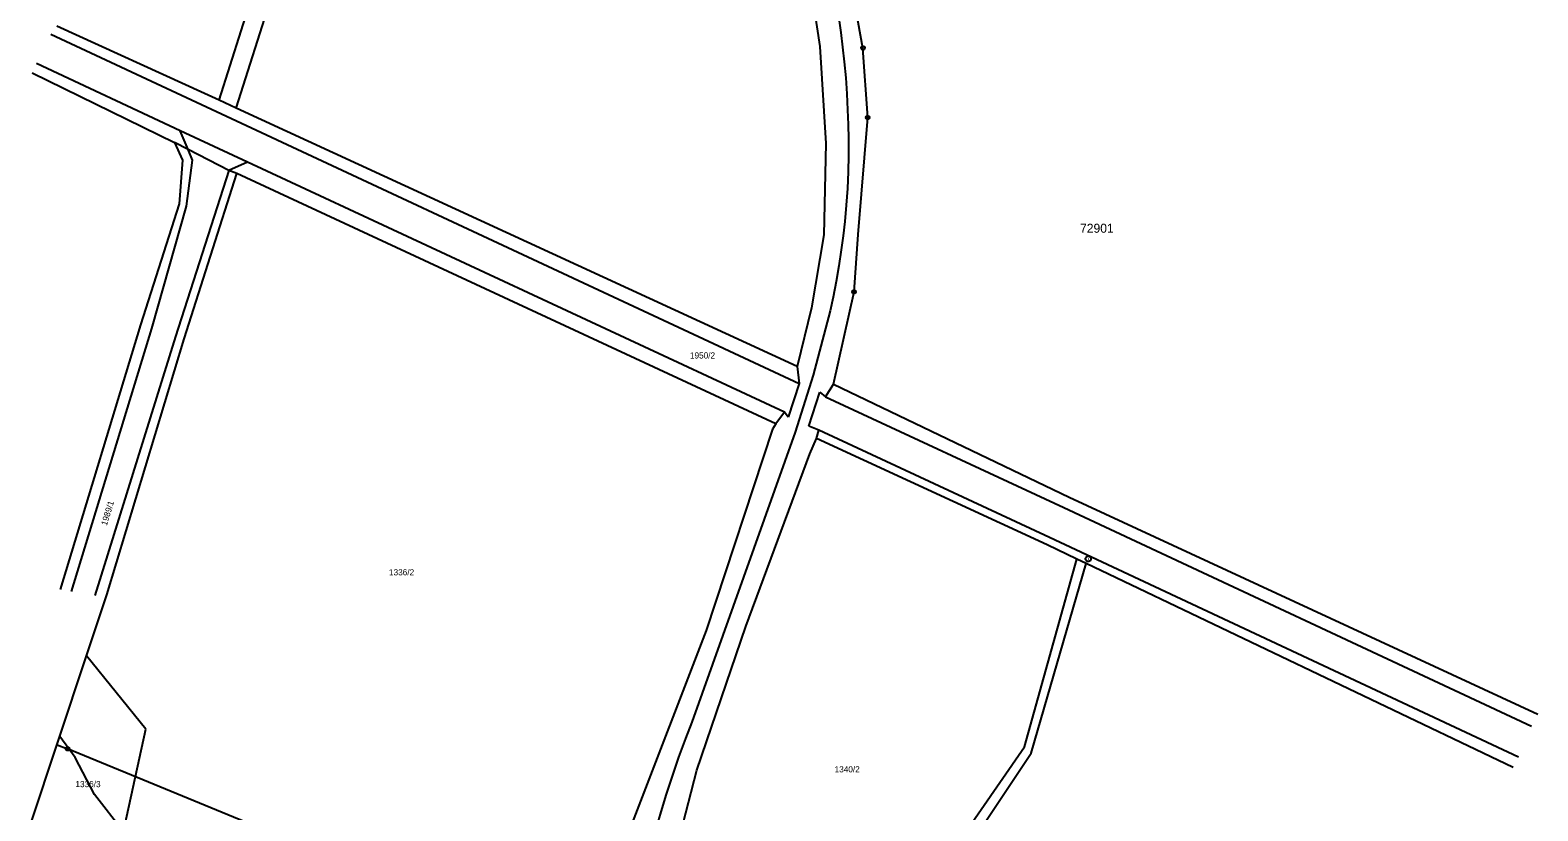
# Model space of a CAD drawing. Extents: x -789470 to -786707, y -1118640 to -1114455.
# Drawn here: x -787470.1 to -787053.8, y -1117519.8 to -1117304.2 of the extents above; entities that cross this region are included whole.
import ezdxf

# ---------------------------------------------------------------- set-up
doc = ezdxf.new("R2010")
doc.units = 0
for name, color, linetype in [('1', 7, 'Continuous'), ('11', 7, 'Continuous'), ('2', 7, 'Continuous'), ('4', 7, 'Continuous'), ('6', 7, 'Continuous'), ('8', 7, 'Continuous')]:
    doc.layers.add(name, color=color, linetype=linetype)

msp = doc.modelspace()

# ---------------------------------------------------------------- linework, layer by layer
at = {"layer": '1'}
for p, q in [((-787417.96, -1117323.48), (-787360.49, -1117143.13)), ((-787413.22, -1117325.67), (-787356.33, -1117146.67)), ((-787255.71, -1117285.12), (-787252.03, -1117308.63)), ((-787240.18, -1117309.09), (-787244.19, -1117287.3)), ((-787422.02, -1117321.61), (-787462.74, -1117303.06)), ((-787252.03, -1117308.63), (-787250.41, -1117335.48)), ((-787238.86, -1117328.3), (-787240.18, -1117309.09)), ((-787469.59, -1117315.99), (-787430.26, -1117335.21)), ((-787417.96, -1117323.48), (-787422.02, -1117321.61)), ((-787413.22, -1117325.67), (-787417.96, -1117323.48)), ((-787258.37, -1117397.06), (-787413.22, -1117325.67)), ((-787241.48, -1117360.62), (-787238.86, -1117328.3)), ((-787430.26, -1117335.21), (-787428.05, -1117340.05)), ((-787426.53, -1117337.12), (-787430.26, -1117335.21)), ((-787250.41, -1117335.48), (-787250.96, -1117360.68)), ((-787415.24, -1117342.91), (-787426.53, -1117337.12)), ((-787428.05, -1117340.05), (-787429.03, -1117352.09)), ((-787427.63, -1117389.42), (-787413.04, -1117343.78)), ((-787413.04, -1117343.78), (-787415.24, -1117342.91)), ((-787264.26, -1117412.91), (-787413.04, -1117343.78)), ((-787429.03, -1117352.09), (-787439.69, -1117385.56)), ((-787250.96, -1117360.68), (-787254.36, -1117380.85)), ((-787242.61, -1117376.43), (-787241.48, -1117360.62)), ((-787248.32, -1117401.92), (-787242.61, -1117376.43)), ((-787254.36, -1117380.85), (-787258.37, -1117397.06)), ((-787439.69, -1117385.56), (-787461.86, -1117458.64)), ((-787448.94, -1117460.1), (-787427.63, -1117389.42)), ((-787258.37, -1117397.06), (-787257.76, -1117401.7)), ((-787257.76, -1117401.7), (-787260.78, -1117411.06)), ((-787250.51, -1117405.41), (-787248.32, -1117401.92)), ((-787248.32, -1117401.92), (-787183.24, -1117433.1)), ((-787255.1, -1117413.5), (-787252.11, -1117404.13)), ((-787252.11, -1117404.13), (-787250.51, -1117405.41)), ((-787261.83, -1117409.67), (-787264.26, -1117412.91)), ((-787260.78, -1117411.06), (-787261.83, -1117409.67)), ((-787265.1, -1117414.39), (-787283.43, -1117469.91)), ((-787264.26, -1117412.91), (-787265.1, -1117414.39)), ((-787252.33, -1117414.61), (-787255.1, -1117413.5)), ((-787252.97, -1117416.89), (-787252.33, -1117414.61)), ((-787254.84, -1117421.14), (-787252.97, -1117416.89)), ((-787189.33, -1117446.27), (-787252.97, -1117416.89)), ((-787272.47, -1117468.81), (-787254.84, -1117421.14)), ((-787183.24, -1117433.1), (-787053.8, -1117493.01)), ((-787181.08, -1117450.22), (-787189.33, -1117446.27)), ((-787195.54, -1117502.09), (-787181.08, -1117450.22)), ((-787193.72, -1117503.85), (-787178.49, -1117451.46)), ((-787178.49, -1117451.46), (-787181.08, -1117450.22)), ((-787060.65, -1117507.79), (-787178.49, -1117451.46)), ((-787454.54, -1117476.95), (-787448.94, -1117460.1)), ((-787286.03, -1117508.52), (-787272.47, -1117468.81)), ((-787283.43, -1117469.91), (-787303.89, -1117523.03)), ((-787470.14, -1117523.83), (-787454.54, -1117476.95)), ((-787438.18, -1117497.19), (-787454.54, -1117476.95)), ((-787448.02, -1117542.27), (-787438.18, -1117497.19)), ((-787270.37, -1117609.83), (-787195.54, -1117502.09)), ((-787265.2, -1117611.01), (-787193.72, -1117503.85)), ((-787297.19, -1117551.99), (-787286.03, -1117508.52))]:
    msp.add_line(p, q, dxfattribs=at)
at = {"layer": '11'}
msp.add_lwpolyline([(-787444.38, -1117525.57), (-787452.36, -1117515.25), (-787457.68, -1117504.99), (-787461.95, -1117499.22), (-787461.95, -1117499.22)], dxfattribs=at)
at = {"layer": '4'}
for p, q in [((-787464.41, -1117305.26), (-787257.76, -1117401.7)), ((-787428.71, -1117331.97), (-787468.36, -1117313.39)), ((-787410.13, -1117340.66), (-787428.71, -1117331.97)), ((-787426.53, -1117337.12), (-787428.71, -1117331.97)), ((-787425.29, -1117340.05), (-787426.53, -1117337.12)), ((-787415.24, -1117342.91), (-787429.99, -1117388.74)), ((-787426.99, -1117352.77), (-787425.29, -1117340.05)), ((-787410.13, -1117340.66), (-787415.24, -1117342.91)), ((-787261.83, -1117409.67), (-787410.13, -1117340.66)), ((-787436.56, -1117386.51), (-787426.99, -1117352.77)), ((-787458.74, -1117459.2), (-787436.56, -1117386.51)), ((-787429.99, -1117388.74), (-787452.26, -1117460.27)), ((-787250.51, -1117405.41), (-787184.71, -1117435.94)), ((-787188.65, -1117444.27), (-787252.33, -1117414.61)), ((-787184.71, -1117435.94), (-787055.59, -1117496.38)), ((-787059.18, -1117504.94), (-787188.65, -1117444.27))]:
    msp.add_line(p, q, dxfattribs=at)
at = {"layer": '6'}
for p, q in [((-787249.2, -1117381.68), (-787253.88, -1117399.41)), ((-787253.88, -1117399.41), (-787258.93, -1117415.14)), ((-787258.93, -1117415.14), (-787287.42, -1117495.28)), ((-787462.71, -1117501.49), (-787459.81, -1117502.65)), ((-787397.87, -1117528.11), (-787459.81, -1117502.65))]:
    msp.add_line(p, q, dxfattribs=at)
for points in [[(-787251.57, -1117278.23), (-787250.57, -1117282.2), (-787249.53, -1117286.69), (-787248.58, -1117291.2), (-787247.73, -1117295.73), (-787246.96, -1117300.28), (-787246.29, -1117304.84), (-787245.78, -1117308.9), (-787245.34, -1117312.88), (-787244.93, -1117317.31), (-787244.62, -1117321.74), (-787244.39, -1117326.17), (-787244.26, -1117330.18)], [(-787244.26, -1117330.18), (-787244.17, -1117334.17), (-787244.17, -1117338.75), (-787244.28, -1117343.32), (-787244.48, -1117347.9), (-787244.79, -1117352.47), (-787245.2, -1117357.03), (-787245.64, -1117360.99), (-787246.14, -1117364.86), (-787246.79, -1117369.21), (-787247.54, -1117373.55), (-787248.37, -1117377.87), (-787249.2, -1117381.68)], [(-787287.42, -1117495.28), (-787289.16, -1117499.78), (-787291.06, -1117504.95), (-787292.86, -1117510.16), (-787294.57, -1117515.39), (-787296.19, -1117520.66), (-787297.52, -1117525.3), (-787298.79, -1117529.97), (-787300.15, -1117535.33), (-787301.41, -1117540.72), (-787302.58, -1117546.13), (-787303.51, -1117550.88)], [(-787459.96, -1117502.17), (-787459.65, -1117502.17), (-787459.4, -1117502.35), (-787459.3, -1117502.64), (-787459.4, -1117502.93), (-787459.65, -1117503.11), (-787459.96, -1117503.11), (-787460.21, -1117502.93), (-787460.31, -1117502.64), (-787460.21, -1117502.35), (-787459.96, -1117502.17), (-787459.93, -1117502.21), (-787459.69, -1117502.21), (-787459.53, -1117502.29), (-787460.09, -1117502.29), (-787460.17, -1117502.37), (-787459.45, -1117502.37), (-787459.45, -1117502.45), (-787460.17, -1117502.45), (-787460.21, -1117502.53), (-787459.41, -1117502.53), (-787459.37, -1117502.61), (-787460.25, -1117502.61), (-787460.25, -1117502.69), (-787459.37, -1117502.69), (-787459.4, -1117502.77), (-787460.21, -1117502.77), (-787460.2, -1117502.85), (-787459.39, -1117502.85), (-787459.44, -1117502.93), (-787460.16, -1117502.93), (-787460.08, -1117503.01), (-787459.52, -1117503.01), (-787459.63, -1117503.09), (-787459.97, -1117503.09)]]:
    msp.add_lwpolyline(points, dxfattribs=at)
at = {"layer": '8'}
for p, q in [((-787240.3, -1117309.09), (-787240.06, -1117309.09)), ((-787238.98, -1117328.3), (-787238.74, -1117328.3)), ((-787242.73, -1117376.43), (-787242.49, -1117376.43)), ((-787177.99, -1117450.16), (-787177.89, -1117450.16))]:
    msp.add_line(p, q, dxfattribs=at)
for points in [[(-787240.03, -1117308.61), (-787239.78, -1117308.79), (-787239.68, -1117309.08), (-787239.78, -1117309.37), (-787240.03, -1117309.55), (-787240.34, -1117309.55), (-787240.59, -1117309.37), (-787240.69, -1117309.08), (-787240.59, -1117308.79), (-787240.34, -1117308.61)], [(-787238.71, -1117327.82), (-787238.46, -1117328), (-787238.36, -1117328.29), (-787238.46, -1117328.58), (-787238.71, -1117328.76), (-787239.02, -1117328.76), (-787239.27, -1117328.58), (-787239.37, -1117328.29), (-787239.27, -1117328), (-787239.02, -1117327.82)], [(-787242.46, -1117375.95), (-787242.21, -1117376.13), (-787242.11, -1117376.42), (-787242.21, -1117376.71), (-787242.46, -1117376.89), (-787242.77, -1117376.89), (-787243.02, -1117376.71), (-787243.12, -1117376.42), (-787243.02, -1117376.13), (-787242.77, -1117375.95)], [(-787177.75, -1117449.44), (-787177.41, -1117449.63), (-787177.22, -1117449.97), (-787177.22, -1117450.36), (-787177.41, -1117450.7), (-787177.75, -1117450.89), (-787178.14, -1117450.89), (-787178.48, -1117450.7), (-787178.67, -1117450.36), (-787178.67, -1117449.97), (-787178.48, -1117449.63), (-787178.14, -1117449.44)]]:
    msp.add_lwpolyline(points, close=True, dxfattribs=at)

# ---------------------------------------------------------------- texts
at = {"layer": '11'}
msp.add_text('72901', height=2.5, dxfattribs=at).set_placement((-787180.22, -1117360.11))
at = {"layer": '2'}
for s, p in [('1950/2', (-787287.95, -1117394.84)), ('1336/2', (-787371.05, -1117454.72)), ('1340/2', (-787248, -1117509.13)), ('1336/3', (-787457.64, -1117513.21))]:
    msp.add_text(s, height=1.7, dxfattribs=at).set_placement(p)
msp.add_text('1989/1', height=1.7, rotation=73.1094, dxfattribs=at).set_placement((-787448.97, -1117441.1))

doc.saveas('drawing.dxf')
